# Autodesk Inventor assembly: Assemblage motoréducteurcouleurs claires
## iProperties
Shininess: 64.0
Length Units: 11269
Angle Units: 11279
Time Units: 11290
Mass Units: 11283
Length Display Precision: 3
Angle Display Precision: 2
Compacted: True
Created: 2004-09
Part Number: Assemblage motoréducteurcouleurs claires
Document SubType Name: Assembly
Designer: Laurent
Density: 0.0
Volumn: 0.0
Area: 0.0
PropertySet Name: Model Information
Control State: 0
Master: False
Checked Out: False
Author: Laurent
